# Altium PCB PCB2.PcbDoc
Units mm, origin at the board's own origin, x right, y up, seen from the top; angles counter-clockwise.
Board outline 83.06 x 42.93 mm, 2 copper layers (Top Layer, Bottom Layer); 50 components, 50 nets, 222 pads, 83 vias.
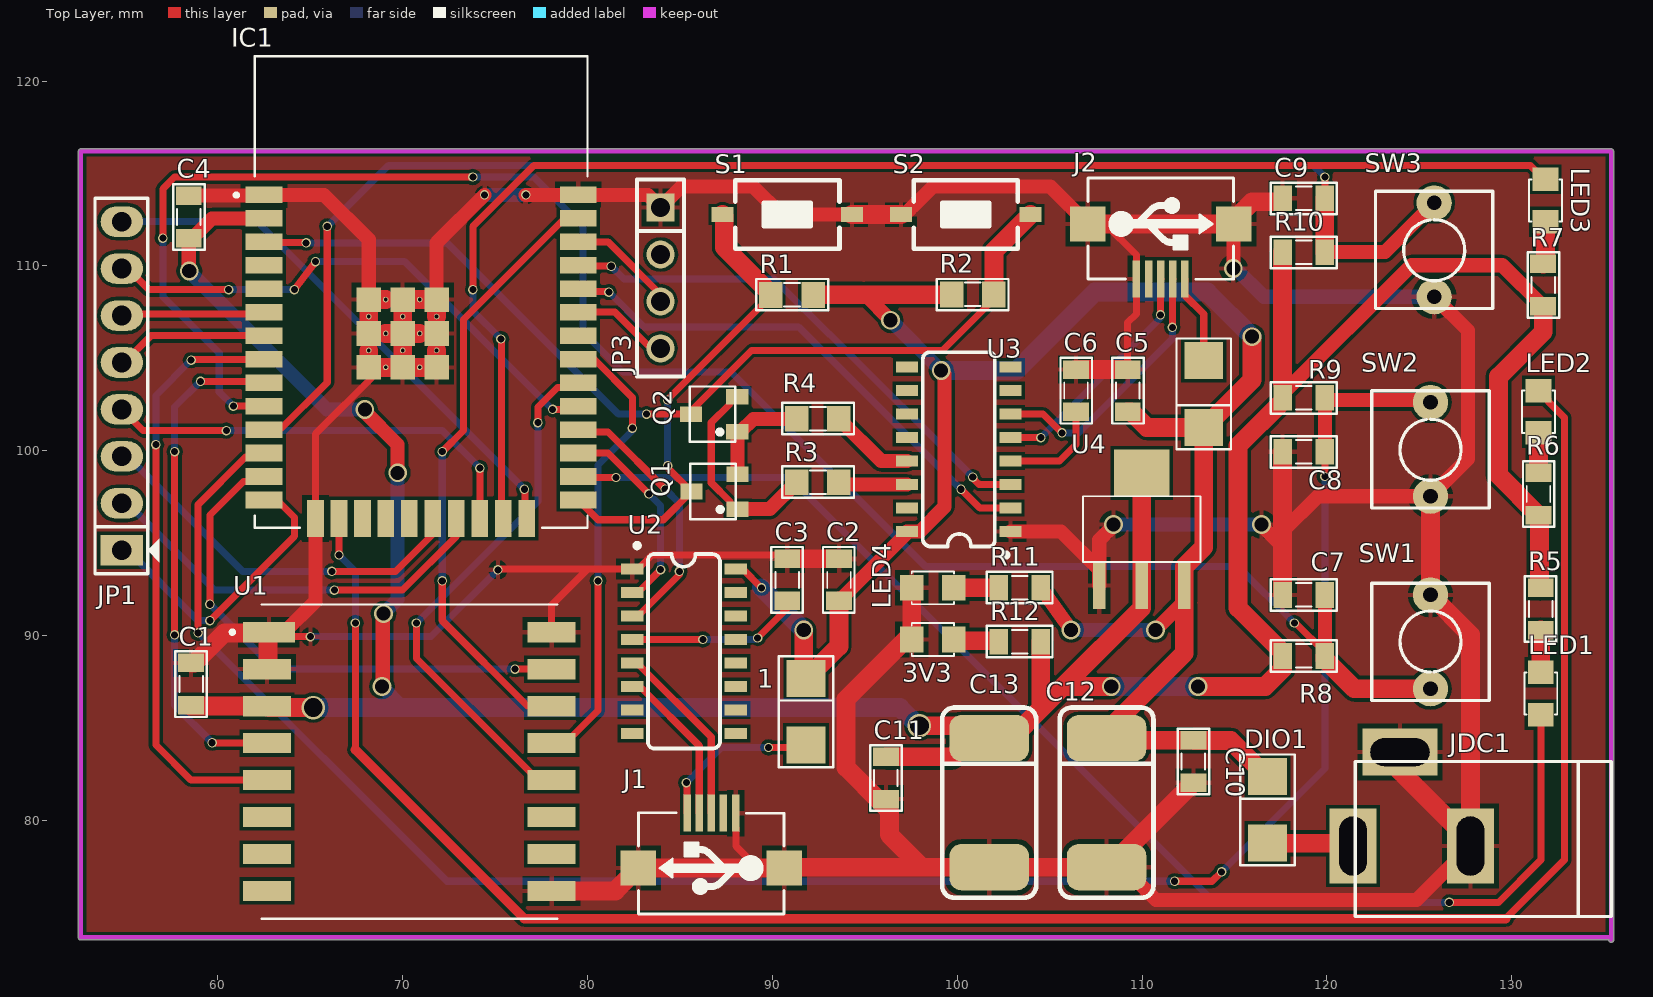
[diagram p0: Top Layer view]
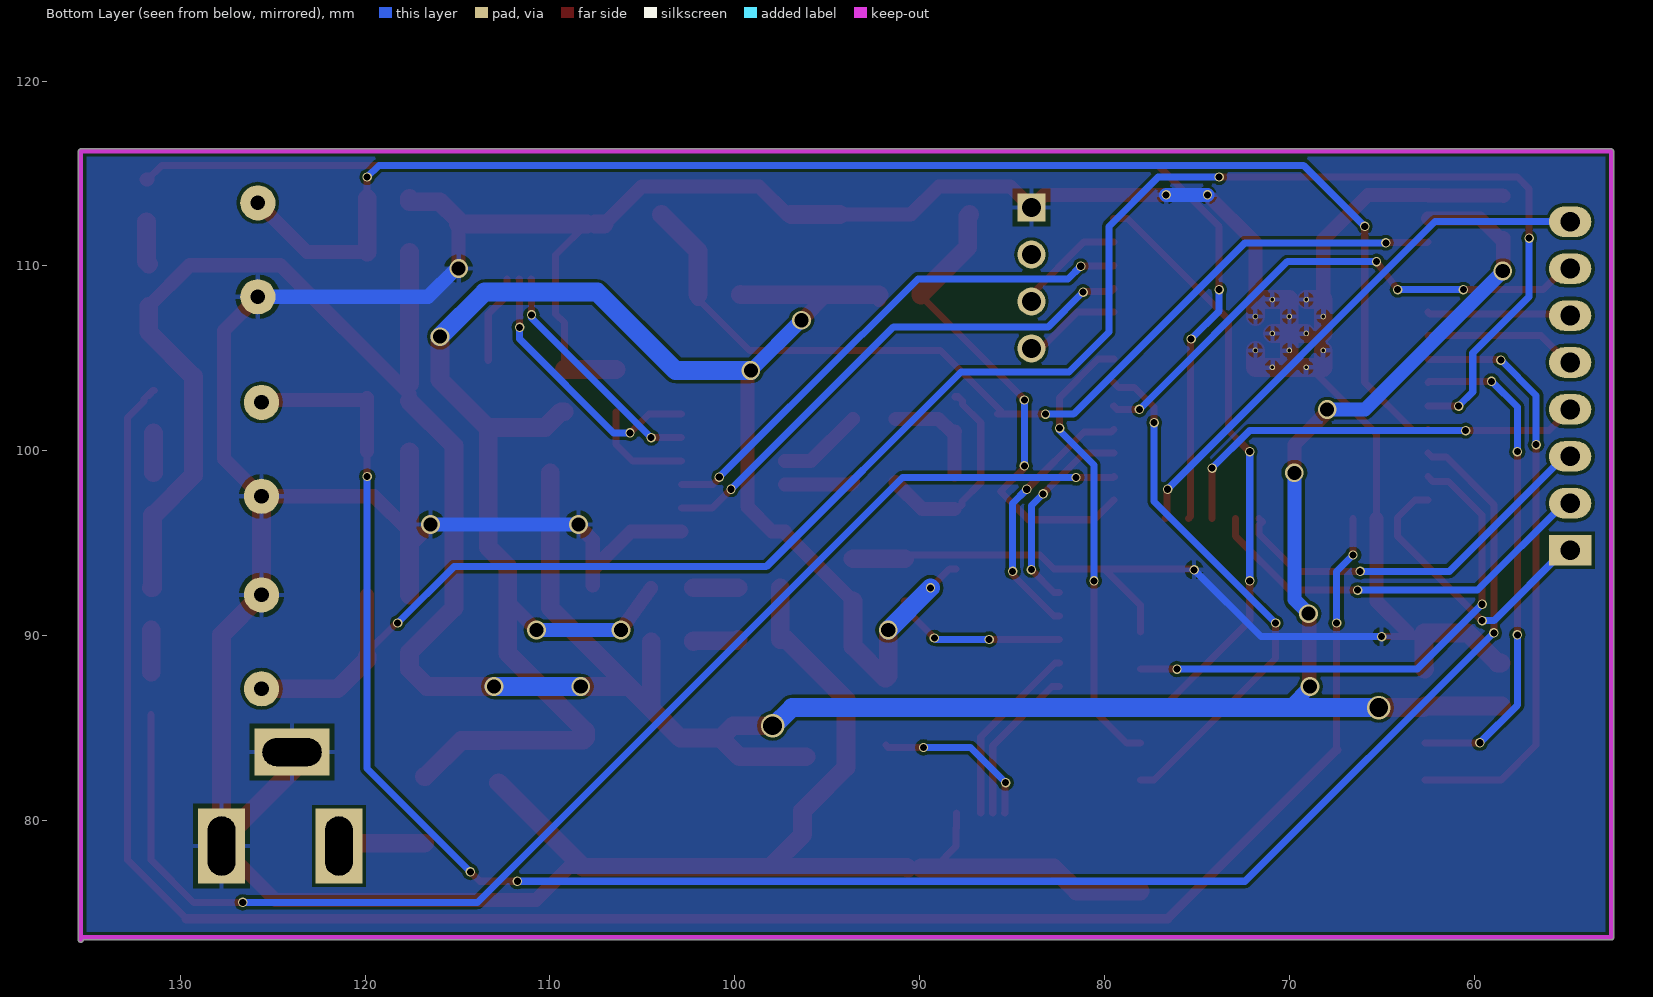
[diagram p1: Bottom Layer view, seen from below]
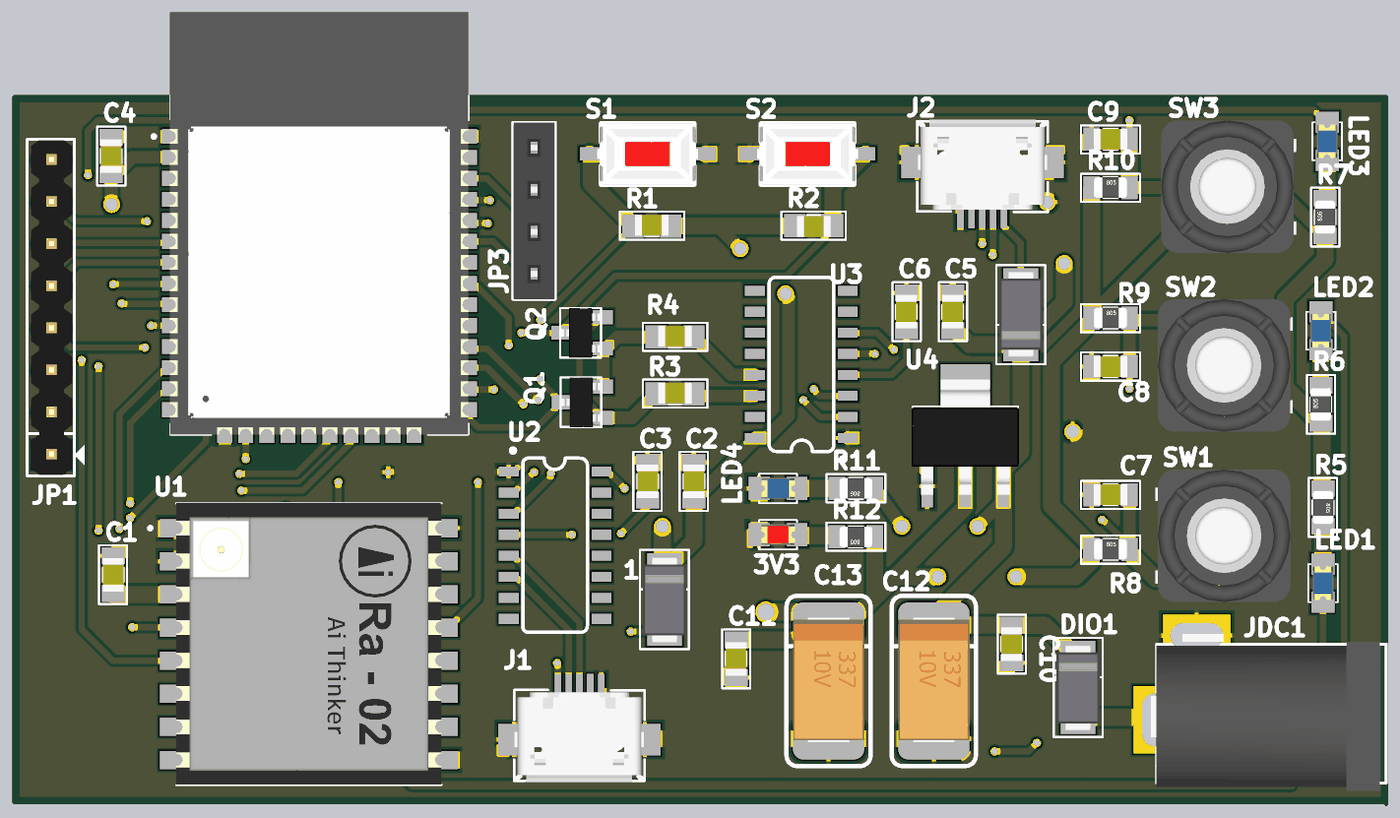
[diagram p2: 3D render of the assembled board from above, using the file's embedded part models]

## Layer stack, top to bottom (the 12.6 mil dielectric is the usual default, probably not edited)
Top Solder: solder mask 0.0102, Solder Resist, Dk 3.5
Top Layer: signal copper 0.0356
Dielectric 1: dielectric 0.32, FR-4, Dk 4.8
Bottom Layer: signal copper 0.0356
Bottom Solder: solder mask 0.0102, Solder Resist, Dk 3.5

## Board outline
52.451,73.66 52.451,73.661 52.451,116.205 cw(c52.578,116.205) 52.578,116.332 135.382,116.332 cw(c135.382,116.205) 135.509,116.205 135.509,73.533 cw(c135.382,73.533) 135.255,73.533 52.578,73.533 cw(c52.578,73.66)

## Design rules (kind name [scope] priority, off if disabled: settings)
Clearance [All] p1: gap=0.178 ignorepadtopadclearanceinfootprint=FALSE
PolygonConnect [All] p1: connectstyle=Relief reliefconductorwidth=0.254 reliefentries=4 polygonreliefangle="90 Angle" airgapwidth=0.254
RoutingVias [All] p1: holewidth=0.762 width=1.016 viastyle="Through Hole" minholewidth=0.381 minwidth=0.508 maxholewidth=1.016 maxwidth=1.27
SolderMaskExpansion [All] p1: expansion=0.102
Width [All] p1: maxlimit=1.016 minlimit=0.381 preferedwidth=0.762
30 further rules are at their usual default settings.

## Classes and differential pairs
component class POWER: 3V3 C10 C11 C12 C13 DIO1 JDC1 LED4 R11 R12 U4
component class MCU: C4 C5 C6 C7 C8 C9 J2 JP1 LED1 LED2 LED3 Q1 Q2 R1 R2 R3 R4 R5 R6 R7 R8 R9 R10 S1 S2 SW1 SW2 SW3
component class LORA: 1 C1 C2 C3 J1 U2
component class HMI: JP3

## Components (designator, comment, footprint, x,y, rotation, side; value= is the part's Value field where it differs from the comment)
1 "S4" DIO-214AC(SMA) 91.872,85.954 r270 top
3V3 "LED" LED-0805-Red 99.822,89.789 r180 top value="LED 3 ly Single Colour" (schematic designator LED5)
C1 "104" CAP_0805 58.547,87.376 r270 top value=33p
C2 "104" CAP_0805 93.599,93.015 r270 top value=33p
C3 "104" CAP_0805 90.805,93.015 r270 top value=33p
C4 "104" CAP_0805 58.42,112.649 r90 top value=33p
C5 "104" CAP_0805 109.22,103.251 r90 top value=33p
C6 "104" CAP_0805 106.426,103.251 r90 top value=33p
C7 "104" CAP_0805 118.745,92.202 r0 top value=33p
C8 "104" CAP_0805 118.745,99.949 r0 top value=33p
C9 "104" CAP_0805 118.745,113.665 r0 top value=33p
C10 "104" CAP_0805 112.776,83.185 r90 top value=33p
C11 "104" CAP_0805 96.139,82.296 r90 top value=33p
C12 "CAP_TAN_SMD" CAP_7343 108.077,81.026 r270 top
C13 "CAP_TAN_SMD" CAP_7343 101.727,81.026 r270 top
DIO1 "Diode SMD" DIO-214AC(SMA) 116.84,80.645 r270 top value=1N5007
IC1 "ESP32-WROOM-32" MODULE_ESP32-WROOM-32 70.993,108.585 r0 top
J1 "USB-5" USB-M1 86.69,80.391 r180 top
J2 "USB-5" USB-M1 111.011,109.3 r0 top
JDC1 "Jac DC" DC-IN 124.587,81.153 r180 top
JP1 "JP8 PIN" JP8 54.8,94.615 r90 top value=JP7
JP3 "JP4" JP4-C1T 83.947,113.157 r270 top
LED1 "LED" LED-0805-Blue 131.572,88.011 r270 top value="LED 3 ly Single Colour"
LED2 "LED" LED-0805-Blue 131.445,100.965 r90 top value="LED 3 ly Single Colour"
LED3 "LED" LED-0805-Blue 131.826,112.395 r90 top value="LED 3 ly Single Colour"
LED4 "LED" LED-0805-Blue 99.822,92.583 r180 top value="LED 3 ly Single Colour"
Q1 "2SC1815" SOT23D 86.868,97.79 r90 top value=C1815
Q2 "2SC1815" SOT23D 86.848,101.981 r90 top value=C1815
R1 "1K" SM-0805 91.059,108.433 r180 top
R2 "1K" SM-0805 100.838,108.458 r0 top
R3 "1K" SM-0805 92.456,98.298 r180 top
R4 "1K" SM-0805 92.456,101.727 r180 top
R5 "Resistor - SMD" RES-SMD-0805 131.572,91.44 r270 top
R6 "Resistor - SMD" RES-SMD-0805 131.445,97.663 r90 top
R7 "Resistor - SMD" RES-SMD-0805 131.699,108.966 r90 top
R8 "Resistor - SMD" RES-SMD-0805 118.745,88.9 r0 top
R9 "Resistor - SMD" RES-SMD-0805 118.745,102.87 r0 top
R10 "Resistor - SMD" RES-SMD-0805 118.745,110.744 r0 top
R11 "Resistor - SMD" RES-SMD-0805 103.378,92.583 r180 top
R12 "Resistor - SMD" RES-SMD-0805 103.378,89.662 r180 top
S1 "SW-SMD" SW-SMD 90.805,112.776 r0 top
S2 "SW-SMD" SW-SMD 100.457,112.776 r180 top
SW1 "SW" SW2 125.603,92.202 r270 top value="SW chip 2 pin"
SW2 "SW" SW2 125.603,97.536 r90 top value="SW chip 2 pin"
SW3 "SW" SW2 125.803,108.331 r90 top value="SW chip 2 pin"
U1 "Ra-02 LoRa" Ra-02 70.358,83.185 r0 top
U2 "CH340C" SOP-16 85.217,89.154 r270 top
U3 "CH340C" SOP-16 100.082,100.076 r90 top
U4 "LM1117-ADJ" LM1117-SOP 109.982,93.98 r0 top
? "S4" DIO-214AC(SMA) 113.284,102.997 r90 top

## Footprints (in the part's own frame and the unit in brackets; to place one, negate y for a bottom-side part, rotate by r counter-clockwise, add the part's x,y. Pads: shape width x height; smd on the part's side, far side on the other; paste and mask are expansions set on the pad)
CAP_0805 [mil]
  rect 39.37x55 smd: 1(-45,0) 2(45,0)
  silkscreen extent -70,-34 70,33, body extent -40,-25 40,25, height 24
CAP_7343 [mm] "Capacitor Tantalum 7343"
  rrect50% 2.5x4.3 smd: 1(-3.429,0) 2(3.556,0)
  silkscreen extent -5.08,-2.54 5.21,2.54, body extent -3.75,-2.14 3.75,2.16, height 2.8
DC-IN [mm] "Jac DC input"
  rect 2.54x4.064 hole 1.5 slot 3.2 at 90 deg: 1(3.175,2.54) 2(-3.175,2.54)
  rect 4.064x2.54 hole 1.5 slot 3.2 at 0 deg: 3(0.635,-2.54)
  silkscreen extent -10.8,-2.03 3.05,6.35, body extent -10.42,-2.67 3.4,6.84, height 11.02
DIO-214AC(SMA) [mm] "DO-214AC Diode Smallest Size"
  rect 2x2.1 smd: 1(1.88,-0.051) 2(-1.732,-0.051)
  silkscreen extent -2.92,-1.52 3.07,1.42, body extent -2.5,-1.35 2.7,1.25, height 2.4
JP4-C1T [mm] "4 row, straight, gold plating"
  rect 1.52x1.52 hole 1.02: 1(0,0)
  round 1.52 hole 1.02: 2(2.54,0) 3(5.08,0) 4(7.62,0)
  silkscreen extent -1.52,-1.27 9.14,1.27, body extent -1.52,-1.25 9.14,1.25, height 8.51
JP8 [mil] "JP8"
  rect 65x90 hole 42: 1(0,0)
  oval 65x90 hole 42: 2(100,0) 3(200,0) 4(300,0) 5(400,0) 6(500,0) 7(600,0) 8(700,0)
  silkscreen extent -50,-80 750,57, body extent -48,-50 748,48, height 354
LED-0805-Blue [mil]
  rect 50x55 smd: 1(0,0) 2(90,0)
  silkscreen extent 0,-35 90,35, body extent 5,-25 85,25, height 43
LED-0805-Red [mil]
  rect 50x55 smd: 1(0,0) 2(90,0)
  silkscreen extent 0,-35 90,35, body extent 5,-25 85,25, height 43
LM1117-SOP [mm]
  rect 0.7x2.54 smd: 1(-2.3,-1.27) 2(0,-1.27) 3(2.3,-1.27)
  rect 3x2.54 smd: 2(0,4.826)
  silkscreen extent -3.17,0 3.17,3.56, body extent -3.25,-1.78 3.25,5.18, height 1.68
MODULE_ESP32-WROOM-32 [mm]
  rect 2x0.9 smd: 1(-8.5,5.26) 2(-8.5,3.99) 3(-8.5,2.72) 4(-8.5,1.45) 5(-8.5,0.18) 6(-8.5,-1.09) 7(-8.5,-2.36) 8(-8.5,-3.63) 9(-8.5,-4.9) 10(-8.5,-6.17) 11(-8.5,-7.44) 12(-8.5,-8.71) 13(-8.5,-9.98) 14(-8.5,-11.25) 25(8.5,-11.25) 26(8.5,-9.98) 27(8.5,-8.71) 28(8.5,-7.44) 29(8.5,-6.17) 30(8.5,-4.9) 31(8.5,-3.63) 32(8.5,-2.36) 33(8.5,-1.09) 34(8.5,0.18) 35(8.5,1.45) 36(8.5,2.72) 37(8.5,3.99) 38(8.5,5.26)
  rect 0.9x2 smd: 15(-5.715,-12.25) 16(-4.445,-12.25) 17(-3.175,-12.25) 18(-1.905,-12.25) 19(-0.635,-12.25) 20(0.635,-12.25) 21(1.905,-12.25) 22(3.175,-12.25) 23(4.445,-12.25) 24(5.715,-12.25)
  rect 1.33x1.33 smd: 39_1(-2.835,-0.405) 39_2(-1,-0.405) 39_3(0.835,-0.405) 39_4(-2.835,-2.24) 39_5(-1,-2.24) 39_6(0.835,-2.24) 39_7(-2.835,-4.075) 39_8(-1,-4.075) 39_9(0.835,-4.075)
  round 0.3 hole 0.2: 39_10(-1.917,-0.405) 39_11(-0.082,-0.405) 39_12(-2.835,-1.322) 39_13(-1,-1.322) 39_14(0.835,-1.322) 39_15(-1.917,-2.24) 39_16(-0.082,-2.24) 39_17(-2.835,-3.157) 39_18(-1,-3.157) 39_19(0.835,-3.157) 39_20(-1.917,-4.075) 39_21(-0.082,-4.075)
  silkscreen extent -10.1,-12.75 9,12.75, body extent -10.54,-12.75 8.98,12.75, height 3.2
Ra-02 [mm]
  rect 2.8x1.1 smd: 1(-7.6,7)
  rect 2.6x1.1 smd: 2(-7.7,5) 3(-7.7,3) 4(-7.7,1) 5(-7.7,-1) 6(-7.7,-3) 7(-7.7,-5) 8(-7.7,-7) 9(7.7,-7) 10(7.7,-5) 11(7.7,-3) 12(7.7,-1) 13(7.7,1) 14(7.7,3) 15(7.7,5) 16(7.7,7)
  silkscreen extent -9.68,-8.5 8,8.5, body extent -8,-8.49 8,8.51, height 3.03
RES-SMD-0805 [mil]
  rect 39.37x55 smd: 1(-45,0) 2(45,0)
  silkscreen extent -70,-34 70,33, body extent -39,-25 39,25, height 31
SM-0805 [mil] "Compoment SMD 80x50mil"
  rect 50x55 smd: 1(-45,0) 2(45,0)
  silkscreen extent -77,-34 76,33, body extent -40,-27 40,23, height 24
SOP-16 [mm]
  rect 0.6x1.2 smd: 1(-4.445,-2.8) 2(-3.175,-2.8) 3(-1.905,-2.8) 4(-0.635,-2.8) 5(0.635,-2.8) 6(1.905,-2.8) 7(3.175,-2.8) 8(4.445,-2.8) 9(4.445,2.8) 10(3.175,2.8) 11(1.905,2.8) 12(0.635,2.8) 13(-0.635,2.8) 14(-1.905,2.8) 15(-3.175,2.8) 16(-4.445,2.8)
  silkscreen extent -5.84,-2.67 5.26,1.95, body extent -4.95,-3.47 4.95,3.47, height 1.75
SOT23D [mm] "SOT 23C - 1-3-2 - BCE"
  rect 0.85x1.2 smd: 1(-0.95,-1.25) 2(0.94,-1.245) 3(0,1.25)
  silkscreen extent -1.5,-1.14 1.5,1.32, body extent -1.5,-1.17 1.5,1.33, height 1.06
SW2 [mil] "SW button 2pin, 250x 250 mil"
  round 75 hole 31: 1(0,0) 2(200,0)
  silkscreen extent -25,-125 225,125, body extent -60,-163 255,157, height 257
SW-SMD [mm] "Switch SMD type"
  rect 1.2x0.8 smd: 1(-3.5,0) 2(3.5,0)
  silkscreen extent -2.82,-1.85 2.82,1.85, body extent -3.05,-1.85 3.05,1.85, height 2.5
USB-M1 [mm]
  rect 0.4x2 smd: 1(1.3,0) 2(0.65,0) 3(0,0) 4(-0.65,0) 5(-1.321,0)
  rect 1.9x1.9 smd: 5(-3.95,2.968) 5(3.95,2.968)
  silkscreen extent -3.94,-0.03 3.94,5.46, body extent -3.98,0.11 4,5.54, height 2.71

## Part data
1 ?: library part "Diode S4", "Dán"
3V3 LED1 LED2 LED3 LED4: "LED Single colour Green and Red"
C1 C2 C3 C4 C5 C6 C7 C8 C9 C10 C11: library part CapSMD, "Capacitor"
C12 C13: "Polazied Tantalum Capacitor"
DIO1: "Default Diode"
IC1: "Bluetooth, WiFi Transceiver Module 2.4GHz ~ 2.5GHz Surface Mount", Package="Module Espressif Systems"
J1 J2: Manufacturer=FCI, Manufacturer Part Number=10118193-0001LF, Supplier Part Number 1=609-4616-1-ND
JDC1: library part DCIN, "Jac DC input"
JP1: library part JP8
JP3: "WR-PHD 2.54 mm Angled Socket Header", Manufacturer="W¨¹rth Elektronik eiSos GmbH", partNo=613004143121
Q1 Q2: library part C1815, "NPN 600mW, ECB"
R1 R2 R3 R4: library part RM, "Resistor SMD"
R5 R6 R7 R8 R9 R10 R11 R12: "Resistor SMD", Manufacturer="Generic Components"
S1 S2: "Switch"
SW1 SW2 SW3: library part SW2, "Switch button 2 pin"
U1: "LoRa Module Ra-02"
U2 U3: "USB to serial chip CH340", Package=Package
U4: "800mA Low-Dropout Linear Regulator"

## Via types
v1: diameter 0.508, hole 0.381, Top Layer to Bottom Layer, 65 vias
v2: diameter 1.016, hole 0.762, Top Layer to Bottom Layer, 16 vias
v3: diameter 1.27, hole 1.016, Top Layer to Bottom Layer, 2 vias

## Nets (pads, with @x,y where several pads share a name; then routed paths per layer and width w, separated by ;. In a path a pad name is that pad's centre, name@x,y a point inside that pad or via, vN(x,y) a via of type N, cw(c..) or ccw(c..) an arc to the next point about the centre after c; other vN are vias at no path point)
3V3: C1.2 C4.1 C11.2 C13.1 IC1.2 R5.1 R6.1 R7.1 R8.1 R9.1 R10.1 R12.1 U1.3 U4.2 | length 179.2
  Top Layer w0.381: C1.2@58.499,86.185 C1.2
  Top Layer w0.762: v2(58.447,109.728) 58.42,109.755 C4.1 58.618,111.506 59.688,112.575 IC1.2 ; v2(67.945,102.235) 67.945,102.108 69.723,100.33 v2(69.723,98.806) ; v2(68.87,87.249) 68.916,87.295 68.916,91.141 v2(68.961,91.186) ; R9.1@117.602,102.687 R9.1 117.602,103.068 124.568,110.035 129.487,110.035 R7.1
  Top Layer w1.016: C1.2@58.499,86.185 U1.3 62.737,86.106 v3(65.151,86.106) ; C11.2 99.748,83.439 C13.1@100.764,84.455 ; v3(97.952,85.125) 100.094,85.125 C13.1@100.764,84.455 ; R12.1 104.521,86.03 ; v2(108.331,87.249) 105.74,87.249 ; U4.2@109.982,98.806 109.982,92.71 109.982,91.491 105.74,87.249 ; v2(113.03,87.249) 116.662,87.249 117.594,88.181 117.594,88.892 R8.1 117.602,89.083 115.189,91.496 115.189,100.275 R9.1@117.602,102.687 ; 117.602,103.632 R10.1 ; R5.1 131.516,92.583 131.508,92.591 131.508,96.512 131.501,96.52 R6.1 129.286,98.679 129.286,104.013 131.699,106.426 R7.1 ; C13.1@100.764,84.455 C13.1 102.946,84.455 104.521,86.03 ; 104.521,86.03 105.74,87.249
  Bottom Layer w0.762: v2(58.447,109.728) 58.447,109.695 65.907,102.235 v2(67.945,102.235) ; v2(68.87,87.249) 68.87,87.229 69.993,86.106 ; v2(68.961,91.186) 69.723,91.948 v2(69.723,98.806)
  Bottom Layer w1.016: v3(65.151,86.106) 69.993,86.106 96.902,86.106 97.883,85.125 v3(97.952,85.125) ; v2(108.331,87.249) v2(113.03,87.249)
+3V3: JP3.2
+5V: 1.2 ?.2 C2.2 C5.1 C10.2 C12.1 DIO1.2 R1.1 R2.1 R11.1 U2.16 U3.16 U4.3 | length 109.6
  Top Layer w0.381: U2.16 88.392,93.599 v1(89.408,92.583)
  Top Layer w0.762: R1.1@92.202,108.152 R1.1 ; C2.2 97.282,95.555 U3.16 97.975,95.631 99.314,96.97 99.314,104.15 v2(99.129,104.336) ; 94.869,108.445 95.009,108.445 v2(96.393,107.061) ; R11.1 v2(106.155,90.297) ; v2(110.727,90.297) U4.3@112.282,91.852
  Top Layer w1.016: v2(91.694,90.297) 91.694,87.813 1.2 91.871,87.686 93.599,89.414 C2.2 ; R1.1 92.215,108.445 94.869,108.445 ; 95.009,108.445 99.682,108.445 R2.1 ; C5.1 109.403,102.108 110.246,101.265 ?.2 ; U4.3@112.282,91.708 112.282,89.041 108.077,84.836 C12.1 108.196,84.336 112.768,84.336 C10.2 112.784,84.32 114.797,84.32 116.739,82.377 DIO1.2 ; U4.3@112.282,91.852 U4.3 112.282,93.732 113.335,94.785 ?.2 ; v2(115.951,106.172) 115.951,103.831 113.385,101.265 ?.2
  Bottom Layer w0.762: v2(96.393,107.061) 96.403,107.061 v2(99.129,104.336) ; v2(106.155,90.297) v2(110.727,90.297)
  Bottom Layer w1.016: v1(89.408,92.583) v2(91.694,90.297) ; v2(99.129,104.336) 103.193,104.336 107.442,108.585 113.538,108.585 v2(115.951,106.172)
GND: 3V3.2 C1.1 C2.1 C3.1 C4.2 C5.2 C6.2 C7.1 C8.1 C9.1 C10.1 C11.1 C12.2 C13.2 IC1.1 IC1.15 IC1.38 IC1.39_1 IC1.39_2 IC1.39_3 IC1.39_4 IC1.39_5 IC1.39_6 IC1.39_7 IC1.39_8 IC1.39_9 IC1.39_10 IC1.39_11 IC1.39_12 IC1.39_13 IC1.39_14 IC1.39_15 IC1.39_16 IC1.39_17 IC1.39_18 IC1.39_19 IC1.39_20 IC1.39_21 J1.5 J2.5 JDC1.2 JDC1.3 JP3.1 LED4.2 S1.2 S2.2 SW1.1 SW2.1 SW3.1 U1.1 U1.2 U1.9 U1.16 U2.1 U3.1 U4.1 | length 326.2
  Top Layer w0.381: U1.2 U1.2@62.666,88.185 ; U1.1@62.708,90.143 62.911,89.94 63.608,89.94 v1(65,89.94) ; IC1.15 65.278,100.918 68.514,104.154 68.87,104.51 IC1.39_20 ; v1(75.144,93.559) 75.184,93.599 80.01,93.599 ; U1.16 78.058,91.647 80.01,93.599 ; J1.5@88.011,80.391 88.011,79.591 88.02,79.581 88.02,78.604 89.201,77.423 ; J1.5@89.916,77.423 J1.5@90.64,77.423 ; C3.1 90.602,94.361 83.479,94.361 82.717,93.599 U2.1 80.01,93.599 ; J2.5@107.552,112.268 108.006,112.268 109.69,110.584 109.69,109.3 109.69,107.404 109.22,106.934 C5.2
  Top Layer w0.762: C4.2 58.447,113.818 62.466,113.818 IC1.1 65.733,113.845 68.158,111.42 IC1.39_1 ; U1.1@63.608,90.185 65.278,91.855 IC1.15 ; IC1.39_3 71.828,111.251 v1(74.422,113.845) ; v1(76.655,113.845) IC1.38 83.259,113.845 JP3.1 85.09,114.3 88.953,114.3 90.477,112.776 S1.2 ; S2.2 97.157,112.776 98.681,114.3 105.029,114.3 J2.5@107.061,112.268 ; U3.1 105.619,95.631 U4.1@107.682,93.568 ; U4.1 U4.1@107.682,93.568 ; C12.2 108.204,77.47 108.977,77.47 110.755,75.692 124.841,75.692 127.381,78.232 127.762,77.851 127.762,78.232 JDC1.2 ; v2(108.458,96.012) 108.458,95.943 107.682,95.167 U4.1@107.682,93.568 ; v2(114.935,109.855) 114.948,109.868 114.948,112.255 J2.5@114.961,112.268 ; v2(116.459,96.012) 116.459,95.963 117.602,94.82 117.602,94.785 ; 117.602,95.631 119.507,97.536 SW2.1 127.635,99.568 127.635,106.499 SW3.1
  Top Layer w1.016: C1.1 58.73,88.519 60.353,90.143 62.708,90.143 62.708,88.227 U1.2@62.666,88.185 ; IC1.39_17 IC1.39_7 68.87,104.51 ; IC1.39_4@68.163,106.345 68.158,106.34 IC1.39_4 IC1.39_12 IC1.39_1 IC1.39_10 ; IC1.39_20 IC1.39_8 ; IC1.39_15 IC1.39_5 ; IC1.39_16 IC1.39_5 ; IC1.39_19 IC1.39_9 IC1.39_21 IC1.39_8 ; IC1.39_14 IC1.39_3 IC1.39_11 IC1.39_2 IC1.39_13 IC1.39_5 ; U1.9 81.502,76.185 82.74,77.423 89.201,77.423 J1.5@89.916,77.423 ; J1.5@90.64,77.423 90.687,77.47 98.09,77.47 ; C3.1 C2.1 ; S1.2 S2.2 ; LED4.2 3V3.2 97.211,89.789 93.98,86.558 93.98,82.867 95.917,80.931 96.329,80.518 96.329,79.231 98.09,77.47 ; C6.2 C5.2 ; J2.5@107.061,112.268 J2.5@107.552,112.268 ; J2.5@108.006,112.268 114.961,112.268 114.961,112.485 115.951,113.474 117.594,113.474 117.602,113.482 C9.1 ; C12.2 C13.2 98.09,77.47 ; C12.2@108.204,77.47 C10.1 ; C7.1 117.602,94.785 ; 117.602,94.82 117.602,95.631 C8.1 ; JDC1.3 124.714,83.693 123.825,82.804 127.762,78.867 JDC1.2 ; SW2.1 SW1.1 127.762,90.043 JDC1.2@127.762,79.375 ; IC1.39_8 IC1.39_18 IC1.39_5
  Bottom Layer w0.381: v1(65,89.94) 71.525,89.94 v1(75.144,93.559)
  Bottom Layer w0.762: v1(74.422,113.845) v1(76.655,113.845) ; v2(108.458,96.012) v2(116.459,96.012) ; v2(114.935,109.855) 115.062,109.855 116.586,108.331 SW3.1
GPIO0: IC1.25 Q1.3 R1.2 S1.1 | length 26.1
  Top Layer w0.381: IC1.25 80.562,96.266 84.094,96.266 Q1.3 84.352,99.056 84.352,99.163 v1(84.328,99.187) ; v1(84.328,102.743) 84.328,102.781 89.916,108.369 R1.2
  Top Layer w1.016: S1.1 87.397,112.684 87.397,111.015 89.916,108.496 R1.2
  Bottom Layer w0.381: v1(84.328,99.187) v1(84.328,102.743)
GPIO2: IC1.24 JP1.8 | length 29.6
  Top Layer w0.381: JP1.8 JP1.8@54.991,112.395 ; v1(76.581,97.917) 76.605,97.893 76.605,96.438 IC1.24
  Bottom Layer w0.381: JP1.8 62.103,112.395 v1(76.581,97.917)
GPIO4: IC1.26 LED1.2 | length 70.5
  Top Layer w0.381: IC1.26@79.464,98.576 IC1.26 79.546,98.552 v1(81.534,98.552) ; v1(126.619,75.565) 129.286,75.565 131.572,77.851 LED1.2
  Bottom Layer w0.381: v1(81.534,98.552) 90.932,98.552 113.919,75.565 v1(126.619,75.565)
GPIO5: IC1.29 JP1.7 | length 30.9
  Top Layer w0.381: JP1.7@54.91,110.258 54.26,110.435 54.643,109.765 55.208,109.765 56.261,108.712 v1(60.579,108.712) ; v1(64.135,108.712) v1(65.278,110.236) ; v1(78.105,102.235) 79.313,102.235 IC1.29
  Bottom Layer w0.381: v1(60.579,108.712) v1(64.135,108.712) ; v1(65.278,110.236) 70.104,110.236 v1(78.105,102.235)
GPIO12: IC1.14 JP1.1 | length 15.9
  Top Layer w0.381: v1(59.563,90.805) 64.135,95.377 64.135,96.393 63.193,97.335 IC1.14
  Bottom Layer w0.381: JP1.1 55.118,94.615 58.928,90.805 v1(59.563,90.805)
GPIO13: IC1.16 LED2.2 | length 109.8
  Top Layer w0.381: v1(66.548,94.361) IC1.16 ; 67.437,83.82 v1(67.437,90.678) ; 129.667,74.676 132.842,77.851 132.842,101.79 131.953,102.679 131.953,102.806 131.508,103.251 LED2.2 ; LED2.2@131.381,103.251 LED2.2 ; LED2.2@131.699,102.997 LED2.2
  Top Layer w0.508: 67.437,83.82 76.581,74.676 129.667,74.676
  Bottom Layer w0.381: v1(66.548,94.361) 67.437,93.472 v1(67.437,90.678)
GPIO15: IC1.23 LED3.2 | length 76.2
  Top Layer w0.381: v1(73.787,108.712) 73.787,112.141 77.089,115.443 131,115.443 LED3.2@131.762,114.681 ; v1(75.311,106.045) 75.335,106.021 75.335,96.438 IC1.23
  Top Layer w0.762: LED3.2@131.762,114.681 LED3.2
  Bottom Layer w0.381: v1(73.787,108.712) 73.787,107.569 v1(75.311,106.045)
GPIO21: IC1.33 JP3.4 | length 5.3
  Top Layer w0.381: IC1.33 81.481,107.495 83.439,105.537 JP3.4
GPIO22: IC1.36 JP3.3 | length 6
  Top Layer w0.381: IC1.36 81.1,111.305 83.947,108.458 JP3.3
GPIO25: C7.2 IC1.10 R8.2 SW1.2 | length 102
  Top Layer w0.381: v1(57.023,111.506) 57.023,114.173 57.658,114.808 v1(73.787,114.808) ; v1(60.833,102.415) IC1.10 ; v1(118.237,90.678) 118.308,90.678 119.888,89.098 R8.2
  Top Layer w0.762: R8.2@119.888,89.098 C7.2
  Top Layer w1.016: R8.2 119.888,88.717 121.483,87.122 SW1.2
  Bottom Layer w0.381: v1(57.023,111.506) 57.023,108.331 60.071,105.283 60.071,103.177 v1(60.833,102.415) ; v1(73.787,114.808) 77.089,114.808 79.756,112.141 79.756,106.426 81.915,104.267 87.757,104.267 98.298,93.726 115.189,93.726 v1(118.237,90.678)
GPIO26: C9.2 IC1.11 R10.2 SW3.2 | length 79.7
  Top Layer w0.381: IC1.11 62.546,101.092 63.303,101.092 65.913,103.702 v1(65.913,112.141) ; C9.2 v1(119.888,114.808)
  Top Layer w0.762: R10.2 123.136,110.744 SW3.2
  Top Layer w1.016: R10.2 C9.2
  Bottom Layer w0.381: v1(65.913,112.141) 69.215,115.443 119.253,115.443 v1(119.888,114.808)
GPIO27: C8.2 IC1.12 R9.2 SW2.2 | length 106.6
  Top Layer w0.381: v1(58.928,90.143) 58.928,97.081 61.499,99.652 62.27,99.652 IC1.12 ; v1(111.76,76.708) 113.792,76.708 v1(114.3,77.216) ; v1(119.888,98.605) C8.2
  Top Layer w0.762: C8.2 119.888,102.862 120.007,102.743 125.476,102.743 SW2.2
  Bottom Layer w0.381: v1(58.928,90.143) 58.955,90.143 72.39,76.708 84.548,76.708 v1(111.76,76.708) ; v1(114.3,77.216) 119.888,82.804 v1(119.888,98.605)
GPIO34: IC1.6 JP1.6 | length 7.8
  Top Layer w0.381: JP1.6 54.89,107.405 62.403,107.405 IC1.6
GPIO35: IC1.7 JP1.5 | length 8.3
  Top Layer w0.381: JP1.5 54.92,104.775 56.37,106.225 IC1.7
Net1_1: 1.1 J1.1 | length 9
  Top Layer w0.381: v1(85.344,82.042) 85.344,81.915 85.381,81.878 85.381,80.4 J1.1 ; v1(89.789,83.947) 91.694,83.947 1.1
  Bottom Layer w0.381: v1(85.344,82.042) 87.249,83.947 v1(89.789,83.947)
Net3V3_1: 3V3.1 R12.2 | length 2.5
  Top Layer w1.016: 3V3.1 99.885,89.725 102.227,89.725 102.235,89.718 R12.2
Net_1: ?.1 J2.1 | length 4.8
  Top Layer w0.381: J2.1 112.311,108.415 113.335,107.391 ?.1
NetC3_2: C3.2 U2.4 | length 9.8
  Top Layer w0.381: U2.4 v1(86.233,89.789) ; v1(89.201,89.87) 90.904,91.574 90.706,91.773 90.607,91.872 C3.2
  Bottom Layer w0.381: v1(86.233,89.789) 89.12,89.789 v1(89.201,89.87)
NetC6_1: C6.1 U3.4 | length 5.7
  Top Layer w0.381: U3.4 105.537,99.441 106.426,100.33 C6.1
NetDIO1_1: DIO1.1 JDC1.1 | length 4.7
  Top Layer w1.016: DIO1.1 121.26,78.765 JDC1.1
NetIC1_8: IC1.8 U1.5 | length 32.4
  Top Layer w0.381: v1(56.642,100.33) 56.642,84.074 58.531,82.185 U1.5 ; v1(58.547,104.902) 58.571,104.926 62.464,104.926 IC1.8
  Bottom Layer w0.381: v1(56.642,100.33) 56.642,102.997 v1(58.547,104.902)
NetIC1_9: IC1.9 U1.4 | length 27.4
  Top Layer w0.381: v1(57.658,90.043) v1(57.658,99.949) ; v1(59.055,103.759) 59.079,103.735 62.443,103.735 IC1.9 ; v1(59.69,84.201) 59.698,84.193 62.65,84.193 U1.4
  Bottom Layer w0.381: v1(57.658,90.043) 57.658,86.233 v1(59.69,84.201) ; v1(57.658,99.949) 57.658,102.362 v1(59.055,103.759)
NetIC1_13: IC1.13 U1.15 | length 28.6
  Top Layer w0.381: v1(59.563,91.694) 59.563,96.52 61.388,98.345 62.233,98.345 IC1.13 ; v1(76.073,88.185) U1.15
  Bottom Layer w0.381: v1(59.563,91.694) 63.072,88.185 v1(76.073,88.185)
NetIC1_27: IC1.27 U2.2 | length 11.1
  Top Layer w0.381: IC1.27 81.1,99.875 v1(83.312,97.663) ; U2.2 82.717,92.329 83.947,93.559 v1(83.947,93.568)
  Bottom Layer w0.381: v1(83.312,97.663) 83.947,97.028 v1(83.947,93.568)
NetIC1_28: IC1.28 U2.3 | length 14.4
  Top Layer w0.381: IC1.28 79.619,101.019 81.099,101.019 v1(84.201,97.917) ; U2.3 82.717,91.059 84.963,93.305 v1(84.963,93.472)
  Bottom Layer w0.381: v1(84.201,97.917) 84.963,97.155 v1(84.963,93.472)
NetIC1_30: IC1.30 U1.12 | length 29.1
  Top Layer w0.381: v1(70.739,90.678) 70.739,88.754 77.308,82.185 U1.12 ; v1(77.308,101.518) 77.308,102.365 78.368,103.425 79.233,103.425 IC1.30
  Bottom Layer w0.381: v1(70.739,90.678) 77.308,97.247 v1(77.308,101.518)
NetIC1_31: IC1.31 U1.13 | length 24.7
  Top Layer w0.381: U1.13 78.808,84.185 80.562,85.939 v1(80.562,92.964) ; IC1.31 80.338,104.955 82.423,102.87 v1(82.423,101.219)
  Bottom Layer w0.381: v1(80.562,92.964) 80.562,99.231 82.423,101.092 v1(82.423,101.219)
NetIC1_37: IC1.37 U1.14 | length 33.1
  Top Layer w0.381: v1(72.136,92.964) 72.136,90.805 76.756,86.185 U1.14 ; v1(72.136,99.949) 73.279,101.092 73.279,107.102 78.752,112.575 IC1.37
  Bottom Layer w0.381: v1(72.136,92.964) v1(72.136,99.949)
NetJ1_2: J1.2 U2.6 | length 8.6
  Top Layer w0.381: U2.6 82.828,87.249 86.04,84.037 J1.2
NetJ1_3: J1.3 U2.5 | length 10.1
  Top Layer w0.381: U2.5 82.677,88.519 86.69,84.506 J1.3
NetJ2_2: J2.2 U3.6 | length 14.5
  Top Layer w0.381: U3.6 104.648,101.981 v1(105.664,100.965) ; v1(111.633,106.68) 111.652,106.699 111.652,109.291 J2.2
  Bottom Layer w0.381: v1(105.664,100.965) 106.553,100.965 111.633,106.045 v1(111.633,106.68)
NetJ2_3: J2.3 U3.5 | length 12.9
  Top Layer w0.381: U3.5 v1(104.521,100.711) ; v1(110.998,107.349) 111.005,107.356 111.005,109.294 J2.3
  Bottom Layer w0.381: v1(104.521,100.711) 110.998,107.188 v1(110.998,107.349)
NetLED1_1: LED1.1 R5.2 | length 2.3
  Top Layer w1.016: LED1.1 R5.2
NetLED2_1: LED2.1 R6.2 | length 2.2
  Top Layer w1.016: R6.2 LED2.1
NetLED3_1: LED3.1 R7.2 | length 2.3
  Top Layer w1.016: R7.2 131.826,110.236 LED3.1
NetLED4_1: LED4.1 R11.2 | length 2.4
  Top Layer w1.016: LED4.1 R11.2
NetQ1_1: Q1.1 Q2.2 R3.2 | length 11.3
  Top Layer w0.381: Q2.2 87.918,102.921 87.683,102.686 87.683,102.511 86.69,101.518 86.69,98.268 87.709,97.249 87.709,97.074 87.943,96.84 Q1.1
  Top Layer w0.762: Q1.1 89.855,96.84 R3.2
NetQ1_2: Q1.2 Q2.1 R4.2 | length 5.8
  Top Layer w0.381: Q1.2@88.093,98.71 88.105,98.723 Q1.2
  Top Layer w0.762: Q1.2@88.105,98.723 88.105,101.024 Q2.1 88.273,101.031 88.969,101.727 R4.2
NetR3_1: R3.1 U3.14 | length 3.7
  Top Layer w0.762: R3.1 93.726,98.171 U3.14
NetR4_1: R4.1 U3.13 | length 4.6
  Top Layer w0.762: R4.1 95.885,99.441 U3.13
nRST: IC1.3 Q2.3 R2.2 S2.1 | length 51.7
  Top Layer w0.381: IC1.3 62.522,111.276 64.746,111.276 v1(64.77,111.252) ; v1(83.185,101.981) Q2.3 85.773,101.981 85.598,102.156 88.869,105.428 99.205,105.428 R2.2@101.981,108.204
  Top Layer w0.762: R2.2@101.981,108.204 R2.2
  Top Layer w1.016: R2.2 101.981,110.8 S2.1
  Bottom Layer w0.381: v1(64.77,111.252) 72.39,111.252 81.661,101.981 v1(83.185,101.981)
RX0: IC1.34 U3.2 | length 28.3
  Top Layer w0.381: IC1.34 79.649,108.609 81.129,108.609 v1(81.153,108.585) ; v1(100.203,97.917) 101.219,96.901 U3.2
  Bottom Layer w0.381: v1(81.153,108.585) 83.039,106.699 91.421,106.699 v1(100.203,97.917)
SCK: IC1.20 JP1.3 | length 21.4
  Top Layer w0.381: JP1.3 JP1.3@54.991,99.695 ; v1(66.167,93.472) 69.596,93.472 71.628,95.504 71.628,95.978 71.45,96.157 IC1.20
  Bottom Layer w0.381: JP1.3 55.118,99.695 61.341,93.472 v1(66.167,93.472)
SD0: IC1.21 JP1.2 | length 22.2
  Top Layer w0.381: v1(66.294,92.456) 69.977,92.456 72.898,95.377 IC1.21
  Bottom Layer w0.381: JP1.2 55.118,97.155 59.817,92.456 v1(66.294,92.456)
SDI: IC1.22 JP1.4 | length 23.4
  Top Layer w0.381: JP1.4 55.944,101.092 v1(60.452,101.092) ; IC1.22 v1(74.168,99.06)
  Bottom Layer w0.381: v1(60.452,101.092) 72.136,101.092 v1(74.168,99.06)
TX0: IC1.35 U3.3 | length 28.3
  Top Layer w0.381: IC1.35 79.522,110.006 81.256,110.006 v1(81.28,109.982) ; v1(100.838,98.576) 100.838,98.542 100.965,98.415 100.965,98.394 101.188,98.171 U3.3
  Bottom Layer w0.381: v1(81.28,109.982) 81.962,109.3 90.09,109.3 93.091,106.299 93.115,106.299 v1(100.838,98.576)
pads on no net: IC1.4 IC1.5 IC1.17 IC1.18 IC1.19 IC1.32 J1.4 J2.4 U1.6 U1.7 U1.8 U1.10 U1.11 U2.7 U2.8 U2.9 U2.10 U2.11 U2.12 U2.13 U2.14 U2.15 U3.7 U3.8 U3.9 U3.10 U3.11 U3.12 U3.15

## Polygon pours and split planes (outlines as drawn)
GND on Top Layer (solid, remove dead copper, pour order 12): 52.578,116.205 135.382,116.205 135.382,73.533 135.255,73.66 52.578,73.66 52.578,116.205
no net on Top Layer (solid, pour order 10): 52.578,116.205
no net on Top Layer "Top Layer-No Net" (solid, pour order 0): 48.514,116.713
GND on Bottom Layer (solid, remove dead copper, pour order 14): 135.382,116.205 135.382,73.66 52.578,73.66 52.578,116.205

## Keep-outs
Keep-Out Layer:
  lines w0.254: 135.382,73.533 135.382,74.295 ; 135.382,73.724 135.382,116.205 ; 135.382,73.736 135.382,73.66 114.681,73.66 73.279,73.66 52.578,73.66 52.578,116.205 135.382,116.205 ; 135.382,116.205 135.382,116.205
